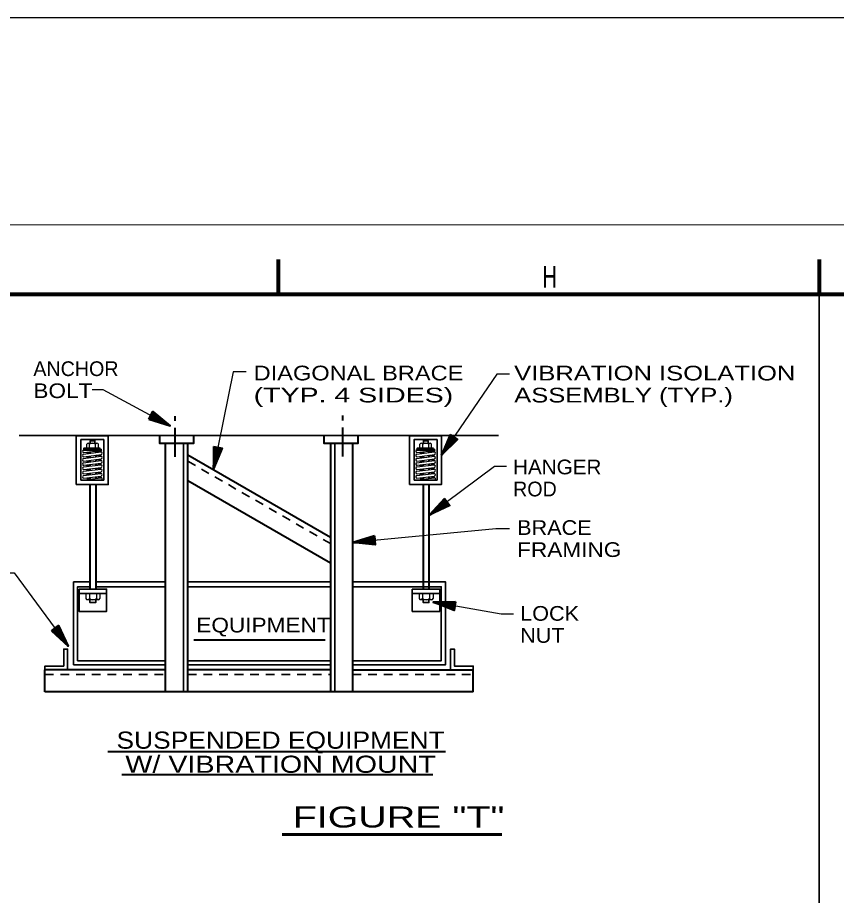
# Model space of a CAD drawing. Extents: x 55 to 190, y 198 to 264.
# Drawn here: x 126.14 to 140.29, y 246.26 to 261.43 of the extents above; entities that cross this region are included whole.
import ezdxf
from ezdxf.enums import TextEntityAlignment as Align

# ---------------------------------------------------------------- set-up
doc = ezdxf.new("R2010")
doc.units = 0
doc.header["$LTSCALE"] = 0.1
doc.linetypes.add('DOT_DASHED', pattern=[7.7, 5, -1.2, 0.3, -1.2])
doc.linetypes.add('SHORT_DASHED', pattern=[2.7, 1.5, -1.2])
for name, color, linetype, lineweight in [('1', 7, 'Continuous', 25), ('2', 7, 'Continuous', 40), ('3', 7, 'Continuous', 25)]:
    doc.layers.add(name, color=color, linetype=linetype, lineweight=lineweight)

msp = doc.modelspace()

# ---------------------------------------------------------------- linework, layer by layer
at = {"layer": '1', "lineweight": 80}
for p, q in [((130.6427, 257.2525), (130.6427, 256.6525)), ((139.9927, 257.2525), (139.9927, 256.6525))]:
    msp.add_line(p, q, dxfattribs=at)
at = {"layer": '1', "lineweight": 13}
msp.add_lwpolyline([(62.4915, 257.8525), (146.5927, 257.8525), (146.5927, 198.4512), (62.4915, 198.4512)], close=True, dxfattribs=at)
at = {"layer": '1', "lineweight": 80}
msp.add_lwpolyline([(65.1915, 256.6525), (145.3927, 256.6525), (145.3927, 199.6512), (65.1915, 199.6512)], close=True, dxfattribs=at)
at = {"layer": '2', "lineweight": 35}
for p, q in [((139.9927, 256.6525), (139.9927, 199.6512)), ((126.1687, 254.2086), (134.4507, 254.2086)), ((129.0064, 254.0808), (129.0064, 249.7811)), ((131.6244, 249.7811), (131.6244, 254.0808)), ((127.1077, 251.684), (127.1077, 250.2483)), ((127.3914, 251.684), (127.1077, 251.684)), ((128.7, 251.684), (127.4906, 251.684)), ((131.5474, 251.684), (129.0836, 251.684)), ((133.1482, 251.684), (132.8645, 251.684)), ((127.6798, 251.4802), (127.2035, 251.4802)), ((128.7, 251.5988), (127.4906, 251.5988)), ((131.5474, 251.5988), (129.0836, 251.5988)), ((133.4366, 251.4802), (132.9603, 251.4802)), ((129.0836, 250.3193), (131.5474, 250.3193)), ((127.1077, 250.2483), (128.7, 250.2483)), ((129.0836, 250.2483), (131.5474, 250.2483))]:
    msp.add_line(p, q, dxfattribs=at)
at = {"layer": '2'}
for p, q in [((128.7807, 254.3787), (128.4172, 254.5103)), ((128.7807, 254.3787), (128.427, 254.5293)), ((128.7807, 254.3787), (128.4354, 254.5441)), ((128.4436, 254.56), (128.7807, 254.3787)), ((128.7807, 254.3787), (128.4529, 254.5767)), ((128.7807, 254.3787), (128.4706, 254.6095)), ((133.4646, 253.8686), (133.6332, 254.2166)), ((133.4646, 253.8686), (133.6511, 254.2049)), ((128.7, 249.7811), (128.7, 254.0808)), ((129.0836, 249.7811), (129.0836, 254.0808)), ((131.5474, 254.0808), (131.5474, 249.7811)), ((131.9308, 254.0808), (131.9308, 249.7811)), ((133.4646, 253.8686), (133.6649, 254.1949)), ((133.6797, 254.1851), (133.4646, 253.8686)), ((133.4646, 253.8686), (133.6956, 254.174)), ((133.4646, 253.8686), (133.7263, 254.1531)), ((127.2813, 253.9626), (127.6001, 253.9626)), ((127.393, 253.9306), (127.393, 253.9025)), ((127.4927, 253.9427), (127.4927, 253.9141)), ((127.5716, 253.9835), (127.5716, 253.9626)), ((129.5266, 253.6332), (129.5469, 254.0192)), ((129.5266, 253.6332), (129.5681, 254.0155)), ((129.5266, 253.6332), (129.5848, 254.0115)), ((129.6022, 254.0083), (129.5266, 253.6332)), ((129.5266, 253.6332), (129.621, 254.0041)), ((129.5266, 253.6332), (129.6575, 253.9967)), ((133.0381, 253.9626), (133.3569, 253.9626)), ((133.1498, 253.9306), (133.1498, 253.9025)), ((133.2495, 253.9427), (133.2495, 253.9141)), ((133.3283, 253.9835), (133.3283, 253.9626)), ((127.393, 253.8567), (127.393, 253.8282)), ((127.393, 253.7832), (127.393, 253.7546)), ((127.4927, 253.87), (127.4927, 253.8414)), ((127.4927, 253.7956), (127.4927, 253.766)), ((131.5474, 252.4478), (129.0836, 253.8702)), ((133.1498, 253.8567), (133.1498, 253.8282)), ((133.1498, 253.7832), (133.1498, 253.7546)), ((133.2495, 253.87), (133.2495, 253.8414)), ((133.2495, 253.7956), (133.2495, 253.766)), ((127.393, 253.7096), (127.393, 253.6803)), ((127.393, 253.6361), (127.393, 253.6067)), ((127.4927, 253.721), (127.4927, 253.6924)), ((127.4927, 253.6474), (127.4927, 253.6189)), ((133.1498, 253.7096), (133.1498, 253.6803)), ((133.1498, 253.6361), (133.1498, 253.6067)), ((133.2495, 253.721), (133.2495, 253.6924)), ((133.2495, 253.6474), (133.2495, 253.6189)), ((127.393, 253.5617), (127.393, 253.5329)), ((127.393, 253.4871), (127.393, 253.4577)), ((127.4927, 253.5731), (127.4927, 253.5445)), ((127.4927, 253.4995), (127.4927, 253.4702)), ((133.1498, 253.5617), (133.1498, 253.5329)), ((133.1498, 253.4871), (133.1498, 253.4577)), ((133.2495, 253.5731), (133.2495, 253.5445)), ((133.2495, 253.4995), (133.2495, 253.4702)), ((127.393, 253.363), (127.393, 251.5567)), ((127.4927, 253.3612), (127.4927, 251.5567)), ((131.5474, 252.0049), (129.0836, 253.4273)), ((133.1498, 253.363), (133.1498, 251.5567)), ((133.2495, 253.3612), (133.2495, 251.5567)), ((133.2553, 252.8349), (133.5281, 253.1088)), ((133.2553, 252.8349), (133.5413, 253.0918)), ((133.2553, 252.8349), (133.5511, 253.0781)), ((133.562, 253.0638), (133.2553, 252.8349)), ((133.2553, 252.8349), (133.5734, 253.0482)), ((133.2553, 252.8349), (133.5956, 253.0183)), ((131.9337, 252.364), (132.3089, 252.4568)), ((131.9337, 252.364), (132.3116, 252.4354)), ((131.9337, 252.364), (132.3126, 252.4185)), ((132.3147, 252.4007), (131.9337, 252.364)), ((131.9337, 252.364), (132.3161, 252.3817)), ((131.9337, 252.364), (132.3198, 252.3444)), ((133.6975, 251.2638), (133.3207, 251.3302)), ((133.3207, 251.3302), (133.7038, 251.2979)), ((133.3207, 251.3302), (133.6874, 251.2082)), ((133.3207, 251.3302), (133.694, 251.245)), ((133.3207, 251.3302), (133.7004, 251.2815)), ((133.3207, 251.3302), (133.7072, 251.3191)), ((127.0143, 250.5714), (126.7736, 250.8691)), ((126.7879, 250.8799), (127.0143, 250.5714)), ((127.0143, 250.5714), (126.8035, 250.891)), ((127.0143, 250.5714), (126.8336, 250.913)), ((127.0143, 250.5714), (126.7426, 250.8466)), ((127.0143, 250.5714), (126.7595, 250.8595)), ((129.1895, 250.6809), (131.4578, 250.6809)), ((128.7, 250.1645), (126.6151, 250.1645)), ((126.6151, 249.7811), (126.6151, 250.1645)), ((131.5474, 250.1645), (129.0839, 250.1645)), ((131.9306, 250.1645), (134.0157, 250.1645)), ((134.0157, 249.7811), (134.0157, 250.1645)), ((134.0157, 249.7811), (126.6151, 249.7811)), ((127.7015, 248.7513), (133.5353, 248.7513)), ((127.9441, 248.3513), (133.317, 248.3513))]:
    msp.add_line(p, q, dxfattribs=at)
at = {"layer": '2', "linetype": 'DOT_DASHED'}
for p, q in [((128.8625, 253.8419), (128.8625, 254.5468)), ((131.7604, 253.8485), (131.7604, 254.5534))]:
    msp.add_line(p, q, dxfattribs=at)
at = {"layer": '2', "lineweight": 25}
for p, q in [((127.3371, 253.9924), (127.3371, 254.0623)), ((127.3623, 254.0774), (127.5126, 254.0774)), ((127.3869, 253.9924), (127.3869, 254.0623)), ((127.4877, 253.9924), (127.4877, 254.0623)), ((127.5377, 253.9924), (127.5377, 254.0618)), ((133.0939, 253.9924), (133.0939, 254.0623)), ((133.1191, 254.0774), (133.2694, 254.0774)), ((133.1437, 253.9924), (133.1437, 254.0623)), ((133.2445, 253.9924), (133.2445, 254.0623)), ((133.2945, 253.9924), (133.2945, 254.0618)), ((127.3985, 253.9028), (127.2813, 253.9173)), ((127.2816, 253.8885), (127.5821, 253.9255)), ((127.2858, 253.9173), (127.5864, 253.9541)), ((127.3371, 253.9924), (127.5377, 253.9924)), ((127.4927, 253.9369), (127.5842, 253.9258)), ((133.1553, 253.9028), (133.0381, 253.9173)), ((133.0384, 253.8885), (133.3389, 253.9255)), ((133.0426, 253.9173), (133.3432, 253.9541)), ((133.0939, 253.9924), (133.2945, 253.9924)), ((133.2495, 253.9369), (133.3411, 253.9258)), ((127.2813, 253.8147), (127.5819, 253.8514)), ((127.3985, 253.7549), (127.2813, 253.7694)), ((127.2816, 253.7408), (127.5821, 253.7774)), ((127.3985, 253.8292), (127.2818, 253.843)), ((127.2858, 253.7697), (127.5864, 253.8062)), ((127.2861, 253.8432), (127.5866, 253.8803)), ((127.5869, 253.8514), (127.4927, 253.8631)), ((127.5864, 253.7774), (127.4927, 253.789)), ((133.0381, 253.8147), (133.3387, 253.8514)), ((133.1553, 253.7549), (133.0381, 253.7694)), ((133.0384, 253.7408), (133.3389, 253.7774)), ((133.1553, 253.8292), (133.0386, 253.843)), ((133.0426, 253.7697), (133.3432, 253.8062)), ((133.0429, 253.8432), (133.3434, 253.8803)), ((133.3437, 253.8514), (133.2495, 253.8631)), ((133.3432, 253.7774), (133.2495, 253.789)), ((127.2813, 253.6668), (127.5819, 253.7035)), ((127.3985, 253.607), (127.2813, 253.6213)), ((127.2816, 253.5927), (127.5821, 253.6295)), ((127.3985, 253.681), (127.2818, 253.6953)), ((127.2858, 253.6215), (127.5864, 253.6583)), ((127.2861, 253.6956), (127.5866, 253.7324)), ((127.5869, 253.7035), (127.4927, 253.7152)), ((127.5864, 253.6295), (127.4927, 253.6411)), ((133.0381, 253.6668), (133.3387, 253.7035)), ((133.1553, 253.607), (133.0381, 253.6213)), ((133.0384, 253.5927), (133.3389, 253.6295)), ((133.1553, 253.681), (133.0386, 253.6953)), ((133.0426, 253.6215), (133.3432, 253.6583)), ((133.0429, 253.6956), (133.3434, 253.7324)), ((133.3437, 253.7035), (133.2495, 253.7152)), ((133.3432, 253.6295), (133.2495, 253.6411)), ((127.2406, 253.4397), (127.5821, 253.4816)), ((127.2813, 253.5189), (127.5819, 253.5554)), ((127.3985, 253.4591), (127.2813, 253.4734)), ((127.3985, 253.5331), (127.2818, 253.5474)), ((127.2858, 253.4736), (127.5864, 253.5101)), ((127.2861, 253.5477), (127.5866, 253.5845)), ((127.5869, 253.5554), (127.4927, 253.5673)), ((127.5864, 253.4816), (127.4927, 253.4929)), ((132.9974, 253.4397), (133.3389, 253.4816)), ((133.0381, 253.5189), (133.3387, 253.5554)), ((133.1553, 253.4591), (133.0381, 253.4734)), ((133.1553, 253.5331), (133.0386, 253.5474)), ((133.0426, 253.4736), (133.3432, 253.5101)), ((133.0429, 253.5477), (133.3434, 253.5845)), ((133.3437, 253.5554), (133.2495, 253.5673)), ((133.3432, 253.4816), (133.2495, 253.4929)), ((127.5644, 251.4771), (127.3218, 251.4771)), ((127.3218, 251.4771), (127.3218, 251.3929)), ((127.3824, 251.4771), (127.3824, 251.3924)), ((127.5043, 251.4771), (127.5043, 251.3924)), ((127.5644, 251.4771), (127.5644, 251.3924)), ((133.3212, 251.4771), (133.0786, 251.4771)), ((133.0786, 251.4771), (133.0786, 251.3929)), ((133.1392, 251.4771), (133.1392, 251.3924)), ((133.2612, 251.4771), (133.2612, 251.3924)), ((133.3212, 251.4771), (133.3212, 251.3924)), ((127.534, 251.3739), (127.3519, 251.3739)), ((133.2908, 251.3739), (133.1088, 251.3739))]:
    msp.add_line(p, q, dxfattribs=at)
at = {"layer": '2', "linetype": 'SHORT_DASHED', "lineweight": 35}
for p, q in [((129.0836, 253.7662), (131.5474, 252.3438)), ((126.6151, 250.0798), (128.7008, 250.0798)), ((129.0826, 250.0798), (131.5456, 250.0798)), ((131.93, 250.0798), (134.0157, 250.0798))]:
    msp.add_line(p, q, dxfattribs=at)
at = {"layer": '2', "lineweight": 60}
msp.add_line((130.7151, 247.3173), (134.5113, 247.3173), dxfattribs=at)
at = {"layer": '2', "lineweight": 25}
for points in [[(130.0891, 255.3077), (129.8665, 255.3077), (129.5266, 253.6332)], [(134.6423, 255.2685), (134.4198, 255.2685), (133.4646, 253.8686)], [(127.4329, 255.0069), (127.6163, 255.0069), (128.7807, 254.3787)], [(134.5899, 253.6723), (134.3806, 253.6723), (133.2553, 252.8349)], [(134.6423, 252.5994), (134.4068, 252.5994), (131.9337, 252.364)], [(125.8499, 251.8406), (126.0854, 251.8406), (127.0143, 250.5714)], [(134.7076, 251.1209), (134.4983, 251.1209), (133.3207, 251.3302)]]:
    msp.add_lwpolyline(points, dxfattribs=at)
at = {"layer": '2'}
for points in [[(128.4079, 254.4931), (128.4809, 254.6277), (128.7807, 254.3787)], [(128.4079, 254.4931), (128.7807, 254.3787), (128.4616, 254.5936)], [(128.5955, 254.2086), (128.5955, 254.0808), (129.1881, 254.0808), (129.1881, 254.2086)], [(131.4347, 254.2086), (131.4347, 254.0808), (132.0274, 254.0808), (132.0274, 254.2086)], [(133.617, 254.2274), (133.7435, 254.1409), (133.4646, 253.8686)], [(133.617, 254.2274), (133.4646, 253.8686), (133.7112, 254.1636)], [(127.5716, 253.9835), (127.2874, 253.9835), (127.2874, 253.9626)], [(129.5279, 254.0232), (129.6779, 253.9924), (129.5266, 253.6332)], [(129.5279, 254.0232), (129.5266, 253.6332), (129.6395, 254.0007)], [(133.3283, 253.9835), (133.0442, 253.9835), (133.0442, 253.9626)], [(133.5165, 253.1244), (133.6078, 253.0013), (133.2553, 252.8349)], [(133.5165, 253.1244), (133.2553, 252.8349), (133.5847, 253.0333)], [(132.3071, 252.4761), (132.3214, 252.3237), (131.9337, 252.364)], [(132.3071, 252.4761), (131.9337, 252.364), (132.3182, 252.3629)], [(133.7104, 251.3384), (133.6834, 251.1876), (133.3207, 251.3302)], [(133.7104, 251.3384), (133.3207, 251.3302), (133.6908, 251.2262)], [(126.727, 250.8349), (126.8506, 250.9251), (127.0143, 250.5714)], [(126.727, 250.8349), (127.0143, 250.5714), (126.8185, 250.9024)]]:
    msp.add_lwpolyline(points, dxfattribs=at)
at = {"layer": '2', "lineweight": 35}
for points in [[(127.1543, 253.363), (127.7083, 253.363), (127.7083, 254.206), (127.1543, 254.206)], [(132.9111, 253.363), (133.4651, 253.363), (133.4651, 254.206), (132.9111, 254.206)], [(127.2369, 253.4397), (127.6319, 253.4397), (127.6319, 254.1412), (127.2369, 254.1412)], [(132.9937, 253.4397), (133.3887, 253.4397), (133.3887, 254.1412), (132.9937, 254.1412)], [(127.2035, 251.5564), (127.6798, 251.5564), (127.6798, 251.1701), (127.2035, 251.1701)], [(132.9603, 251.5564), (133.4366, 251.5564), (133.4366, 251.1701), (132.9603, 251.1701)]]:
    msp.add_lwpolyline(points, close=True, dxfattribs=at)
for points in [[(127.4787, 254.0779), (127.4787, 254.12), (127.3964, 254.12), (127.3964, 254.0779)], [(133.2355, 254.0779), (133.2355, 254.12), (133.1532, 254.12), (133.1532, 254.0779)], [(131.9308, 250.2483), (133.5329, 250.2483), (133.5329, 251.684), (131.9308, 251.684)], [(127.3914, 251.5988), (127.1786, 251.5988), (127.1786, 250.3193), (128.7, 250.3193)], [(131.9308, 250.3193), (133.4617, 250.3193), (133.4617, 251.5988), (131.9308, 251.5988)], [(127.393, 251.3733), (127.393, 251.3226), (127.4927, 251.3226), (127.4927, 251.3733)], [(133.1498, 251.3733), (133.1498, 251.3226), (133.2495, 251.3226), (133.2495, 251.3733)], [(126.6151, 250.1645), (126.6151, 250.2266), (126.94, 250.2266), (126.94, 250.5206), (127.0059, 250.5206), (127.0059, 250.1658)], [(134.015, 250.1639), (134.015, 250.2261), (133.69, 250.2261), (133.69, 250.5203), (133.6239, 250.5203), (133.6239, 250.1653)]]:
    msp.add_lwpolyline(points, dxfattribs=at)
at = {"layer": '2', "lineweight": 25}
for centre, radius, start, end in [((127.3621, 254.0494), 0.028, 27.8877, 152.03419), ((127.4373, 253.9848), 0.0926, 57.00616, 122.94297), ((127.5125, 254.0492), 0.028, 26.78269, 151.8391), ((133.1189, 254.0494), 0.028, 27.8877, 152.03419), ((133.1941, 253.9848), 0.0926, 57.00616, 122.94297), ((133.2693, 254.0492), 0.028, 26.78269, 151.8391), ((127.3522, 251.4083), 0.0339, 206.78269, 331.8391), ((127.4432, 251.4862), 0.1121, 237.00616, 302.94298), ((127.5342, 251.408), 0.0339, 207.8877, 332.03419), ((133.109, 251.4083), 0.0339, 206.78269, 331.8391), ((133.2, 251.4862), 0.1121, 237.00616, 302.94298), ((133.291, 251.408), 0.0339, 207.8877, 332.03419)]:
    msp.add_arc(centre, radius, start, end, dxfattribs=at)
for centre, major_axis, start_param, end_param in [((127.2836, 253.9398), (0, -0.0227), 3.2517222, 6.3933148), ((127.5843, 253.9028), (0, 0.0227), 3.2517222, 6.3933148), ((133.0404, 253.9398), (0, -0.0227), 3.2517222, 6.3933148), ((133.3411, 253.9028), (0, 0.0227), 3.2517222, 6.3933148), ((127.2836, 253.7919), (0, -0.0227), 3.2517222, 6.3933148), ((127.2839, 253.8658), (0, -0.0227), 3.2517222, 6.3933148), ((127.584, 253.8288), (0, 0.0227), 3.2517222, 6.3933148), ((127.5843, 253.7549), (0, 0.0227), 3.2517222, 6.3933148), ((133.0404, 253.7919), (0, -0.0227), 3.2517222, 6.3933148), ((133.0407, 253.8658), (0, -0.0227), 3.2517222, 6.3933148), ((133.3408, 253.8288), (0, 0.0227), 3.2517222, 6.3933148), ((133.3411, 253.7549), (0, 0.0227), 3.2517222, 6.3933148), ((127.2836, 253.644), (0, -0.0227), 3.2517222, 6.3933148), ((127.2839, 253.7179), (0, -0.0227), 3.2517222, 6.3933148), ((127.2839, 253.57), (0, -0.0227), 3.2517222, 6.3933148), ((127.584, 253.6809), (0, 0.0227), 3.2517222, 6.3933148), ((127.5843, 253.607), (0, 0.0227), 3.2517222, 6.3933148), ((133.0404, 253.644), (0, -0.0227), 3.2517222, 6.3933148), ((133.0407, 253.7179), (0, -0.0227), 3.2517222, 6.3933148), ((133.0407, 253.57), (0, -0.0227), 3.2517222, 6.3933148), ((133.3408, 253.6809), (0, 0.0227), 3.2517222, 6.3933148), ((133.3411, 253.607), (0, 0.0227), 3.2517222, 6.3933148), ((127.2836, 253.4961), (0, -0.0227), 3.2517222, 6.3933148), ((127.584, 253.533), (0, 0.0227), 3.2517222, 6.3933148), ((127.5843, 253.4591), (0, 0.0227), 3.6938927, 6.3879492), ((133.0404, 253.4961), (0, -0.0227), 3.2517222, 6.3933148), ((133.3408, 253.533), (0, 0.0227), 3.2517222, 6.3933148), ((133.3411, 253.4591), (0, 0.0227), 3.6938927, 6.3879492)]:
    msp.add_ellipse(centre, major_axis=major_axis, ratio=0.9, start_param=start_param, end_param=end_param, dxfattribs=at)
at = {"layer": '2'}
for centre in [(127.584, 253.9767), (133.3408, 253.9767)]:
    msp.add_ellipse(centre, major_axis=(0, 0.0227), ratio=0.9, start_param=3.2517222, end_param=4.0304893, dxfattribs=at)
at = {"layer": '3'}
msp.add_line((62.4915, 261.4312), (146.5927, 261.4312), dxfattribs=at)

# ---------------------------------------------------------------- texts
at = {"layer": '1', "width": 0.7}
msp.add_text('H', height=0.375, dxfattribs=at).set_placement((135.3355, 256.765), align=Align.CENTER)
at = {"layer": '2'}
for s, p in [('ANCHOR', (126.4145, 255.2379)), ('ROD', (134.7029, 253.159))]:
    msp.add_text(s, height=0.254, dxfattribs=at).set_placement(p)
for s, width, p in [('DIAGONAL BRACE', 1.2, (130.2203, 255.1627)), ('VIBRATION ISOLATION', 1.3, (134.7219, 255.1617)), ('BOLT', 1.15, (126.4145, 254.8569)), ('(TYP. 4 SIDES)', 1.45, (130.2203, 254.7817)), ('ASSEMBLY (TYP.)', 1.3, (134.7219, 254.7807)), ('HANGER', 1.05, (134.7029, 253.54)), ('BRACE', 1.1, (134.7727, 252.4931)), ('FRAMING', 1.15, (134.7727, 252.1121)), ('LOCK', 1.1, (134.8251, 251.0101)), ('NUT', 1.1, (134.8251, 250.6291))]:
    msp.add_text(s, height=0.254, dxfattribs=dict(at, width=width)).set_placement(p)
for s, height, width, p in [('EQUIPMENT', 0.254, 1.15, (130.3907, 250.8079)), ('SUSPENDED EQUIPMENT', 0.2963, 1.15, (130.6865, 248.799)), ('W/ VIBRATION MOUNT', 0.2963, 1.25, (130.6868, 248.383)), ('FIGURE "T"', 0.3633, 1.4, (132.725, 247.4377))]:
    msp.add_text(s, height=height, dxfattribs=dict(at, width=width)).set_placement(p, align=Align.CENTER)

doc.saveas('drawing.dxf')
